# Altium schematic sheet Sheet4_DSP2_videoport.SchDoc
size A3
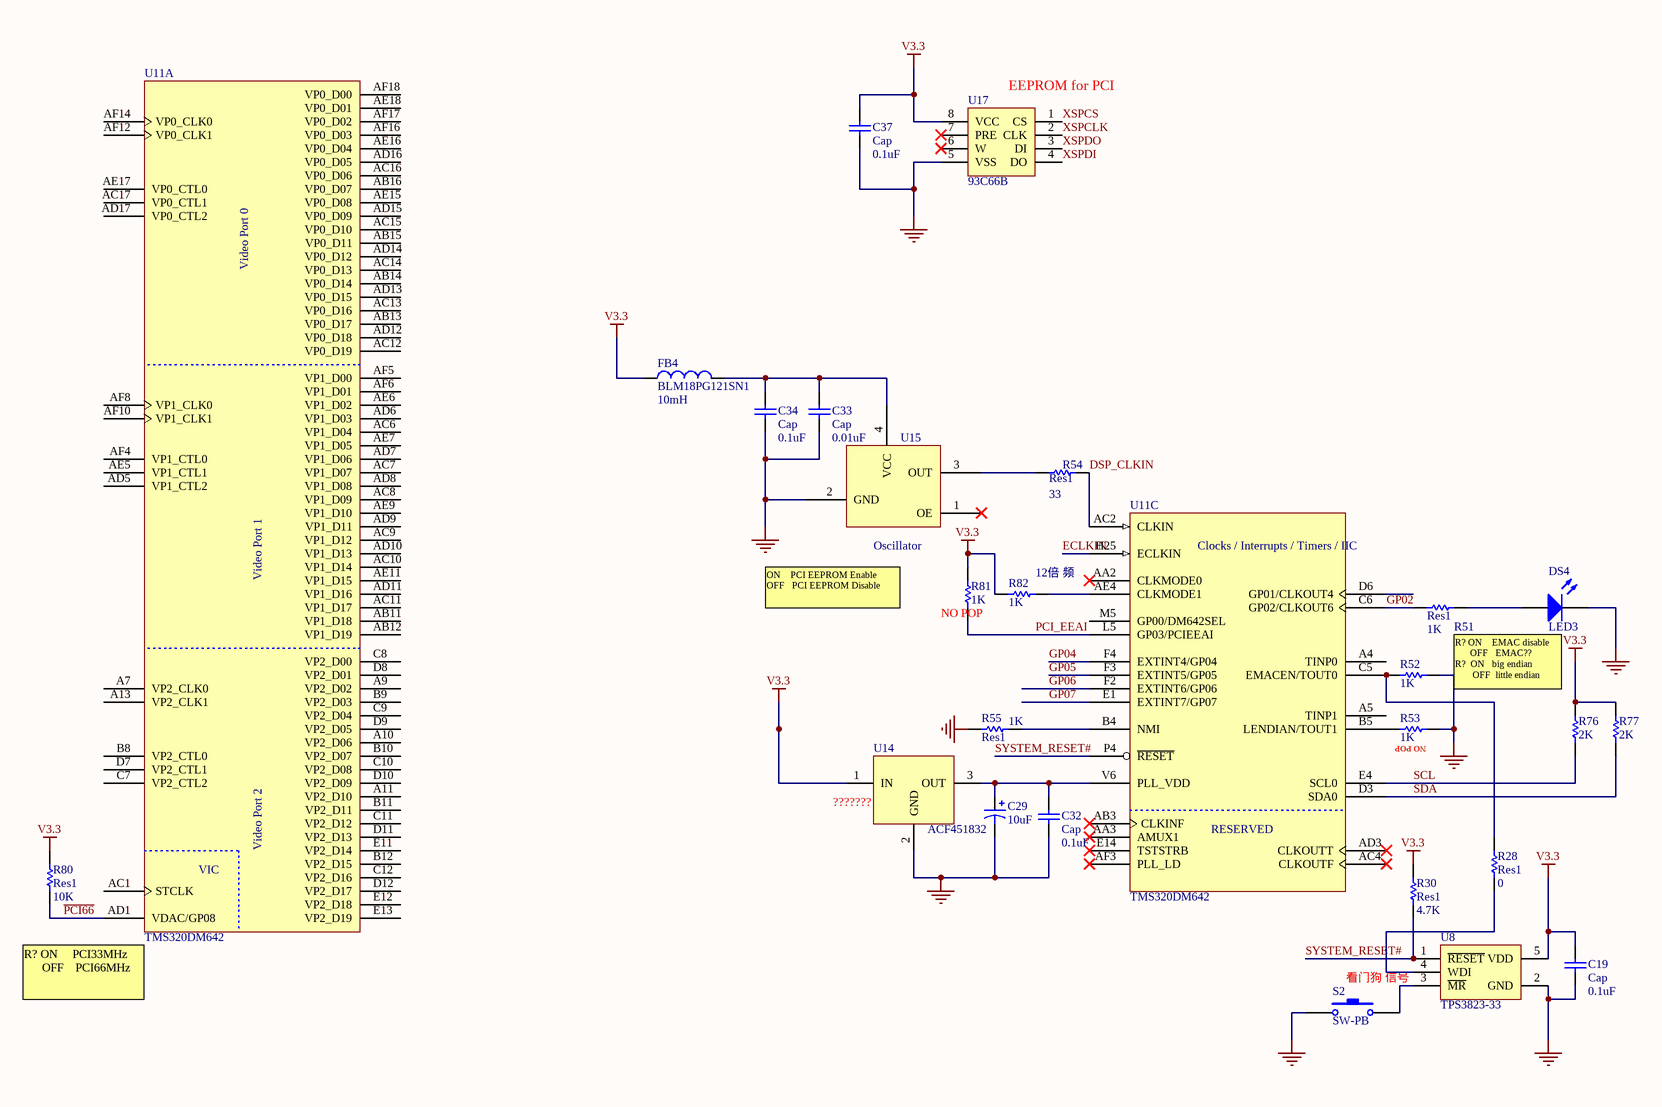
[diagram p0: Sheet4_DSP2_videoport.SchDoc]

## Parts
C19  Cap  value 0.1uF  [C1608-0603]
C29  value 10uF  [CC3216-1206]  (hidden comment: Cap Pol2)
C32  Cap  value 0.1uF  [C1608-0603]
C33  Cap  value 0.01uF  [C1608-0603]
C34  Cap  value 0.1uF  [C1608-0603]
C37  Cap  value 0.1uF  [C1608-0603]
DS4  LED3  [SMD _LED]
FB4  BLM18PG121SN1  value 10mH  [C1608-0603]
R28  Res1  value 0  [CR1608-0603]
R30  Res1  value 4.7K  [CR1608-0603]
R51  Res1  value 1K  [CR1608-0603]
R52  value 1K  [CR1608-0603]  (hidden comment: Res1)
R53  value 1K  [CR1608-0603]  (hidden comment: Res1)
R54  Res1  value 33  [CR1608-0603]
R55  Res1  value 1K  [CR1608-0603]
R76  value 2K  [CR1608-0603]  (hidden comment: Res1)
R77  value 2K  [CR1608-0603]  (hidden comment: Res1)
R80  Res1  value 10K  [CR1608-0603]
R81  value 1K  [C1608-0603]  (hidden comment: Res1)
R82  value 1K  [CR1608-0603]  (hidden comment: Res1)
S2  SW-PB  [BUTTON]
U8  TPS3823-33  [DBV5]
U11  TMS320DM642  [GNZ548]  (parts A,C of 5)
U14  ACF451832  [ACF451832]
U15  Oscillator  [OSC50MHz]
U17  93C66B  [SO-G8]

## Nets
GND: C19.1 C29.2 C32.1 C33.1 C34.1 C37.1 DS4.2(K) R52.1 R53.1 R55.1 S2.1 U8.2(GND) U14.2(GND) U15.2(GND) U17.5(VSS)
V3.3: C19.2 C37.2 FB4.1 R30.2 R76.1 R77.1 R80.2 R81.2 R82.2 U8.5(VDD) U14.1(IN) U17.8(VCC)
DSP_CLKIN: R54.2 U11.AC2(CLKIN)
ECLKIN: U11.H25(ECLKIN)
GP02: R51.1 U11.C6(GP02/CLKOUT6)
GP04: U11.F4(EXTINT4/GP04)
GP05: U11.F3(EXTINT5/GP05)
GP06: U11.F2(EXTINT6/GP06)
GP07: U11.E1(EXTINT7/GP07)
~{PCI66}: R80.1 U11.AD1(VDAC/GP08)
PCI_EEAI: R81.1 U11.L5(GP03/PCIEEAI)
SCL: R76.2 U11.E4(SCL0)
SDA: R77.2 U11.D3(SDA0)
SYSTEM_RESET#: R30.1 U8.1(~{RESET}) U11.P4(~{RESET})
XSPCLK: U17.2(CLK)
XSPCS: U17.1(CS)
XSPDI: U17.4(DO)
XSPDO: U17.3(DI)
NetC29_1: C29.1 C32.2 U11.V6(PLL_VDD) U14.3(OUT)
NetC33_2: C33.2 C34.2 FB4.2 U15.4(VCC)
NetDS4_1: DS4.1(A) R51.2
NetR28_1: R28.1 U8.4(WDI)
NetR28_2: R28.2 R52.2 U11.C5(EMACEN/TOUT0)
NetR53_2: R53.2 U11.B5(LENDIAN/TOUT1)
NetR54_1: R54.1 U15.3(OUT)
NetR55_2: R55.2 U11.B4(NMI)
NetR82_1: R82.1 U11.AE4(CLKMODE1)
NetS2_2: S2.2 U8.3(~{MR})

Not connected (* = marked no-connect by the designer): U11 A4(TINP0) A5(TINP1) A7(VP2_CLK0) A9(VP2_D02) A10(VP2_D06) A11(VP2_D10) A13(VP2_CLK1) AA2(CLKMODE0)* AA3(AMUX1)* AB3(CLKINF)* AB11(VP1_D18) AB12(VP1_D19) AB13(VP0_D17) AB14(VP0_D14) AB15(VP0_D11) AB16(VP0_D07) AC1(STCLK) AC4(CLKOUTF)* AC6(VP1_D04) AC7(VP1_D07) AC8(VP1_D09) AC9(VP1_D12) AC10(VP1_D14) AC11(VP1_D17) AC12(VP0_D19) AC13(VP0_D16) AC14(VP0_D13) AC15(VP0_D10) AC16(VP0_D06) AC17(VP0_CTL1) AD3(CLKOUTT)* AD5(VP1_CTL2) AD6(VP1_D03) AD7(VP1_D06) AD8(VP1_D08) AD9(VP1_D11) AD10(VP1_D13) AD11(VP1_D16) AD12(VP0_D18) AD13(VP0_D15) AD14(VP0_D12) AD15(VP0_D09) AD16(VP0_D05) AD17(VP0_CTL2) AE5(VP1_CTL1) AE6(VP1_D02) AE7(VP1_D05) AE9(VP1_D10) AE11(VP1_D15) AE15(VP0_D08) AE16(VP0_D04) AE17(VP0_CTL0) AE18(VP0_D01) AF3(PLL_LD)* AF4(VP1_CTL0) AF5(VP1_D00) AF6(VP1_D01) AF8(VP1_CLK0) AF10(VP1_CLK1) AF12(VP0_CLK1) AF14(VP0_CLK0) AF16(VP0_D03) AF17(VP0_D02) AF18(VP0_D00) B8(VP2_CTL0) B9(VP2_D03) B10(VP2_D07) B11(VP2_D11) B12(VP2_D15) C7(VP2_CTL2) C8(VP2_D00) C9(VP2_D04) C10(VP2_D08) C11(VP2_D12) C12(VP2_D16) D6(GP01/CLKOUT4) D7(VP2_CTL1) D8(VP2_D01) D9(VP2_D05) D10(VP2_D09) D11(VP2_D13) D12(VP2_D17) E11(VP2_D14) E12(VP2_D18) E13(VP2_D19) E14(TSTSTRB)* M5(GP00/DM642SEL); U15 1(OE)*; U17 6(W)* 7(PRE)*

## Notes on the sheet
- (near U17) EEPROM for PCI
- (near R82) 12倍 频
- ON    PCI EEPROM Enable
  OFF   PCI EEPROM Disable
- (near R81) NO POP
- R? ON    EMAC disable
  OFF   EMAC??
  R?  ON   big endian
  OFF  little endian
- (near R53) NO POP
- (near U14) ???????
- (near U11) R? ON     PCI33MHz
  OFF    PCI66MHz
- (near S2) 看门狗 信号

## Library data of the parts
C19 C32-C34 C37 = Cap: Capacitor
C29 = Cap Pol2: Polarized Capacitor (Axial)
DS4 = LED3: Typical BLUE SiC LED; Revision 1: Jul-2002: Re-released for DXP Platform.; Revision 2: 17-Dec-2003: PCB Footprint replaced.
FB4 = Inductor
R28 R30 R51-R55 R76 R77 R80-R82 = Res1: Resistor
S2 = SW-PB: Switch
U14 = EMI filter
